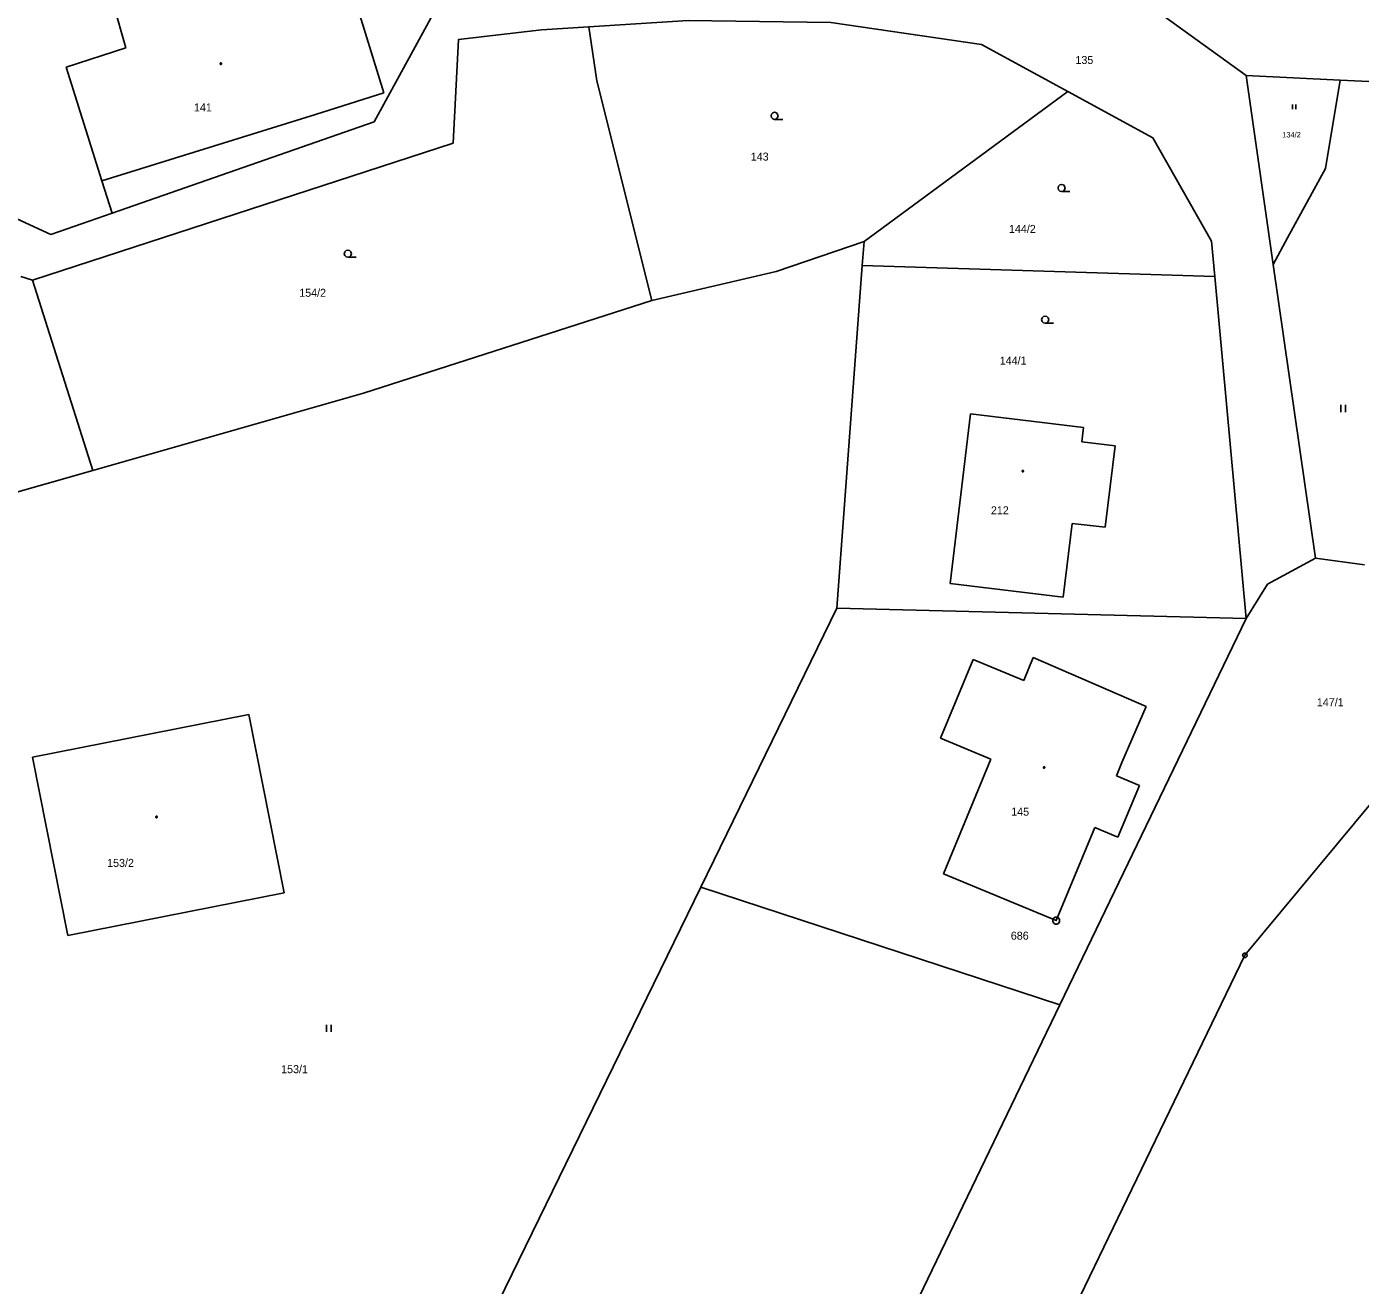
# Model space of a CAD drawing. Extents: x -871430 to -870620, y -1010094 to -1009649.
# Drawn here: x -870778.1 to -870707.3, y -1009951.2 to -1009884.4 of the extents above; entities that cross this region are included whole.
import ezdxf

# ---------------------------------------------------------------- set-up
doc = ezdxf.new("R2010")
doc.units = 0
for name, color, linetype in [('Vrstva 1', 7, 'Continuous'), ('Vrstva 2', 7, 'Continuous'), ('Vrstva 3', 7, 'Continuous'), ('Vrstva 4', 7, 'Continuous'), ('Vrstva 5', 7, 'Continuous'), ('Vrstva 8', 7, 'Continuous')]:
    doc.layers.add(name, color=color, linetype=linetype)

msp = doc.modelspace()

# ---------------------------------------------------------------- linework, layer by layer
at = {"layer": 'Vrstva 1'}
for p, q in [((-870759.65, -1009889.46), (-870755.26, -1009881.44)), ((-870773.49, -1009883.22), (-870772.83, -1009885.52)), ((-870718.85, -1009883.01), (-870713.34, -1009887)), ((-870772.83, -1009885.52), (-870775.99, -1009886.55)), ((-870722.81, -1009887.84), (-870727.39, -1009885.35)), ((-870775.99, -1009886.55), (-870774.1, -1009892.58)), ((-870713.34, -1009887), (-870708.34, -1009887.24)), ((-870713.34, -1009887), (-870711.9, -1009897.02)), ((-870733.63, -1009895.81), (-870722.81, -1009887.84)), ((-870718.29, -1009890.3), (-870722.81, -1009887.84)), ((-870708.34, -1009887.24), (-870703.07, -1009887.49)), ((-870773.56, -1009894.3), (-870759.65, -1009889.46)), ((-870777.78, -1009897.86), (-870755.45, -1009890.59)), ((-870715.17, -1009895.79), (-870718.29, -1009890.3)), ((-870773.56, -1009894.3), (-870774.1, -1009892.58)), ((-870779.56, -1009894.18), (-870776.82, -1009895.44)), ((-870776.82, -1009895.44), (-870773.56, -1009894.3)), ((-870733.73, -1009897.08), (-870733.63, -1009895.81)), ((-870715, -1009897.67), (-870715.17, -1009895.79)), ((-870733.73, -1009897.08), (-870735.07, -1009915.27)), ((-870733.73, -1009897.08), (-870715, -1009897.67)), ((-870711.9, -1009897.02), (-870709.66, -1009912.62)), ((-870777.78, -1009897.86), (-870778.4, -1009897.67)), ((-870715, -1009897.67), (-870713.34, -1009915.82)), ((-870777.78, -1009897.86), (-870774.58, -1009907.96)), ((-870760.21, -1009903.86), (-870744.9, -1009898.93)), ((-870774.58, -1009907.96), (-870760.21, -1009903.86)), ((-870727.98, -1009904.96), (-870729.06, -1009913.97)), ((-870721.97, -1009905.68), (-870727.98, -1009904.96)), ((-870721.97, -1009905.68), (-870722.06, -1009906.45)), ((-870722.06, -1009906.45), (-870720.3, -1009906.66)), ((-870720.3, -1009906.66), (-870720.82, -1009910.98)), ((-870796.84, -1009914.3), (-870774.58, -1009907.96)), ((-870722.58, -1009910.77), (-870723.05, -1009914.69)), ((-870722.58, -1009910.77), (-870720.82, -1009910.98)), ((-870709.66, -1009912.62), (-870712.21, -1009913.99)), ((-870709.66, -1009912.62), (-870707.06, -1009912.97)), ((-870729.06, -1009913.97), (-870723.05, -1009914.69)), ((-870712.21, -1009913.99), (-870713.34, -1009915.82)), ((-870742.3, -1009930.08), (-870735.07, -1009915.27)), ((-870713.34, -1009915.82), (-870735.07, -1009915.27)), ((-870723.23, -1009936.33), (-870713.34, -1009915.82)), ((-870777.79, -1009923.18), (-870766.29, -1009920.91)), ((-870766.29, -1009920.91), (-870764.42, -1009930.39)), ((-870775.91, -1009932.65), (-870777.79, -1009923.18)), ((-870705.48, -1009924.14), (-870713.4, -1009933.7)), ((-870764.42, -1009930.39), (-870775.91, -1009932.65)), ((-870768.7, -1009984.15), (-870742.3, -1009930.08)), ((-870742.3, -1009930.08), (-870723.23, -1009936.33)), ((-870713.4, -1009933.7), (-870732.89, -1009974)), ((-870767.95, -1010029.06), (-870723.23, -1009936.33))]:
    msp.add_line(p, q, dxfattribs=at)
for points in [[(-870727.39, -1009885.35), (-870735.4, -1009884.18), (-870742.97, -1009884.08), (-870748.24, -1009884.41)], [(-870748.24, -1009884.41), (-870750.75, -1009884.57), (-870755.16, -1009885.08), (-870755.45, -1009890.59)], [(-870748.24, -1009884.41), (-870747.81, -1009887.28), (-870744.9, -1009898.93)], [(-870711.9, -1009897.02), (-870711.14, -1009895.61), (-870709.13, -1009891.93), (-870708.34, -1009887.24)], [(-870744.9, -1009898.93), (-870738.29, -1009897.39), (-870733.63, -1009895.81)]]:
    msp.add_lwpolyline(points, dxfattribs=at)
at = {"layer": 'Vrstva 3'}
for p, q in [((-870710.874, -1009888.529), (-870710.874, -1009888.78)), ((-870710.706, -1009888.78), (-870710.706, -1009888.529)), ((-870708.305, -1009904.485), (-870708.305, -1009904.86)), ((-870708.055, -1009904.86), (-870708.055, -1009904.485)), ((-870762.175, -1009937.385), (-870762.175, -1009937.76)), ((-870761.925, -1009937.76), (-870761.925, -1009937.385))]:
    msp.add_line(p, q, dxfattribs=at)
for points in [[(-870738.38, -1009889.32), (-870738.475, -1009889.295), (-870738.542, -1009889.225), (-870738.568, -1009889.132), (-870738.542, -1009889.04), (-870738.475, -1009888.97), (-870738.38, -1009888.945), (-870738.285, -1009888.97), (-870738.218, -1009889.04), (-870738.192, -1009889.132), (-870738.218, -1009889.225), (-870738.285, -1009889.295), (-870738.38, -1009889.32), (-870737.942, -1009889.32)], [(-870723.14, -1009893.15), (-870723.235, -1009893.125), (-870723.302, -1009893.055), (-870723.328, -1009892.962), (-870723.302, -1009892.87), (-870723.235, -1009892.8), (-870723.14, -1009892.775), (-870723.045, -1009892.8), (-870722.978, -1009892.87), (-870722.952, -1009892.962), (-870722.978, -1009893.055), (-870723.045, -1009893.125), (-870723.14, -1009893.15), (-870722.702, -1009893.15)], [(-870761.04, -1009896.64), (-870761.135, -1009896.615), (-870761.202, -1009896.545), (-870761.228, -1009896.452), (-870761.202, -1009896.36), (-870761.135, -1009896.29), (-870761.04, -1009896.265), (-870760.945, -1009896.29), (-870760.878, -1009896.36), (-870760.852, -1009896.452), (-870760.878, -1009896.545), (-870760.945, -1009896.615), (-870761.04, -1009896.64), (-870760.602, -1009896.64)], [(-870724.01, -1009900.14), (-870724.105, -1009900.115), (-870724.172, -1009900.045), (-870724.198, -1009899.952), (-870724.172, -1009899.86), (-870724.105, -1009899.79), (-870724.01, -1009899.765), (-870723.915, -1009899.79), (-870723.848, -1009899.86), (-870723.822, -1009899.952), (-870723.848, -1009900.045), (-870723.915, -1009900.115), (-870724.01, -1009900.14), (-870723.572, -1009900.14)]]:
    msp.add_lwpolyline(points, dxfattribs=at)
at = {"layer": 'Vrstva 4'}
for p, q in [((-870761, -1009881.88), (-870759.12, -1009887.92)), ((-870762.76, -1009889.06), (-870759.12, -1009887.92)), ((-870774.1, -1009892.58), (-870762.76, -1009889.06)), ((-870729.57, -1009922.18), (-870727.83, -1009918)), ((-870725.15, -1009919.11), (-870727.83, -1009918)), ((-870724.65, -1009917.9), (-870725.15, -1009919.11)), ((-870724.65, -1009917.9), (-870718.65, -1009920.49)), ((-870719.93, -1009923.46), (-870718.65, -1009920.49)), ((-870726.89, -1009923.29), (-870729.57, -1009922.18)), ((-870726.89, -1009923.29), (-870729.41, -1009929.37)), ((-870720.23, -1009924.18), (-870719.93, -1009923.46)), ((-870720.23, -1009924.18), (-870719, -1009924.69)), ((-870719, -1009924.69), (-870720.15, -1009927.43)), ((-870723.42, -1009931.86), (-870721.37, -1009926.92)), ((-870721.37, -1009926.92), (-870720.15, -1009927.43)), ((-870729.41, -1009929.37), (-870723.42, -1009931.86))]:
    msp.add_line(p, q, dxfattribs=at)
at = {"layer": 'Vrstva 5'}
for points in [[(-870767.79, -1009886.318), (-870767.765, -1009886.322), (-870767.753, -1009886.345), (-870767.748, -1009886.36), (-870767.753, -1009886.382), (-870767.773, -1009886.4), (-870767.79, -1009886.402), (-870767.812, -1009886.395), (-870767.828, -1009886.38), (-870767.832, -1009886.36), (-870767.828, -1009886.338), (-870767.808, -1009886.32), (-870767.79, -1009886.318)], [(-870725.2, -1009907.958), (-870725.175, -1009907.962), (-870725.162, -1009907.985), (-870725.158, -1009908), (-870725.162, -1009908.022), (-870725.182, -1009908.04), (-870725.2, -1009908.042), (-870725.222, -1009908.035), (-870725.237, -1009908.02), (-870725.242, -1009908), (-870725.237, -1009907.978), (-870725.217, -1009907.96), (-870725.2, -1009907.958)], [(-870724.07, -1009923.688), (-870724.045, -1009923.692), (-870724.032, -1009923.715), (-870724.028, -1009923.73), (-870724.032, -1009923.752), (-870724.052, -1009923.77), (-870724.07, -1009923.772), (-870724.092, -1009923.765), (-870724.107, -1009923.75), (-870724.112, -1009923.73), (-870724.107, -1009923.708), (-870724.087, -1009923.69), (-870724.07, -1009923.688)], [(-870771.2, -1009926.318), (-870771.175, -1009926.322), (-870771.162, -1009926.345), (-870771.158, -1009926.36), (-870771.162, -1009926.382), (-870771.182, -1009926.4), (-870771.2, -1009926.402), (-870771.222, -1009926.395), (-870771.237, -1009926.38), (-870771.242, -1009926.36), (-870771.237, -1009926.338), (-870771.217, -1009926.32), (-870771.2, -1009926.318)]]:
    msp.add_lwpolyline(points, dxfattribs=at)
at = {"layer": 'Vrstva 8'}
for p, q in [((-870723.432, -1009931.86), (-870723.408, -1009931.86)), ((-870713.412, -1009933.7), (-870713.388, -1009933.7))]:
    msp.add_line(p, q, dxfattribs=at)
for points in [[(-870723.372, -1009931.68), (-870723.288, -1009931.728), (-870723.24, -1009931.812), (-870723.24, -1009931.91), (-870723.288, -1009931.995), (-870723.372, -1009932.042), (-870723.47, -1009932.042), (-870723.555, -1009931.995), (-870723.602, -1009931.91), (-870723.602, -1009931.812), (-870723.555, -1009931.728), (-870723.47, -1009931.68), (-870723.372, -1009931.68)], [(-870713.362, -1009933.58), (-870713.3, -1009933.628), (-870713.275, -1009933.7), (-870713.3, -1009933.772), (-870713.362, -1009933.82), (-870713.438, -1009933.82), (-870713.5, -1009933.772), (-870713.525, -1009933.7), (-870713.5, -1009933.628), (-870713.438, -1009933.58), (-870713.362, -1009933.58)]]:
    msp.add_lwpolyline(points, dxfattribs=at)

# ---------------------------------------------------------------- texts
at = {"layer": 'Vrstva 2'}
for s, p in [('135', (-870722.402, -1009886.38)), ('141', (-870769.212, -1009888.9)), ('143', (-870739.642, -1009891.51)), ('144/2', (-870725.932, -1009895.35)), ('154/2', (-870763.622, -1009898.74)), ('144/1', (-870726.422, -1009902.34)), ('212', (-870726.891, -1009910.29)), ('147/1', (-870709.582, -1009920.48)), ('145', (-870725.812, -1009926.29)), ('153/2', (-870773.822, -1009929.01)), ('153/1', (-870764.582, -1009939.96))]:
    msp.add_text(s, height=0.425, dxfattribs=at).set_placement(p)
msp.add_text('134/2', height=0.285, rotation=0.34378, dxfattribs=at).set_placement((-870711.42, -1009890.284))
at = {"layer": 'Vrstva 8'}
msp.add_text('686', height=0.425, dxfattribs=at).set_placement((-870725.834, -1009932.872))

doc.saveas('drawing.dxf')
